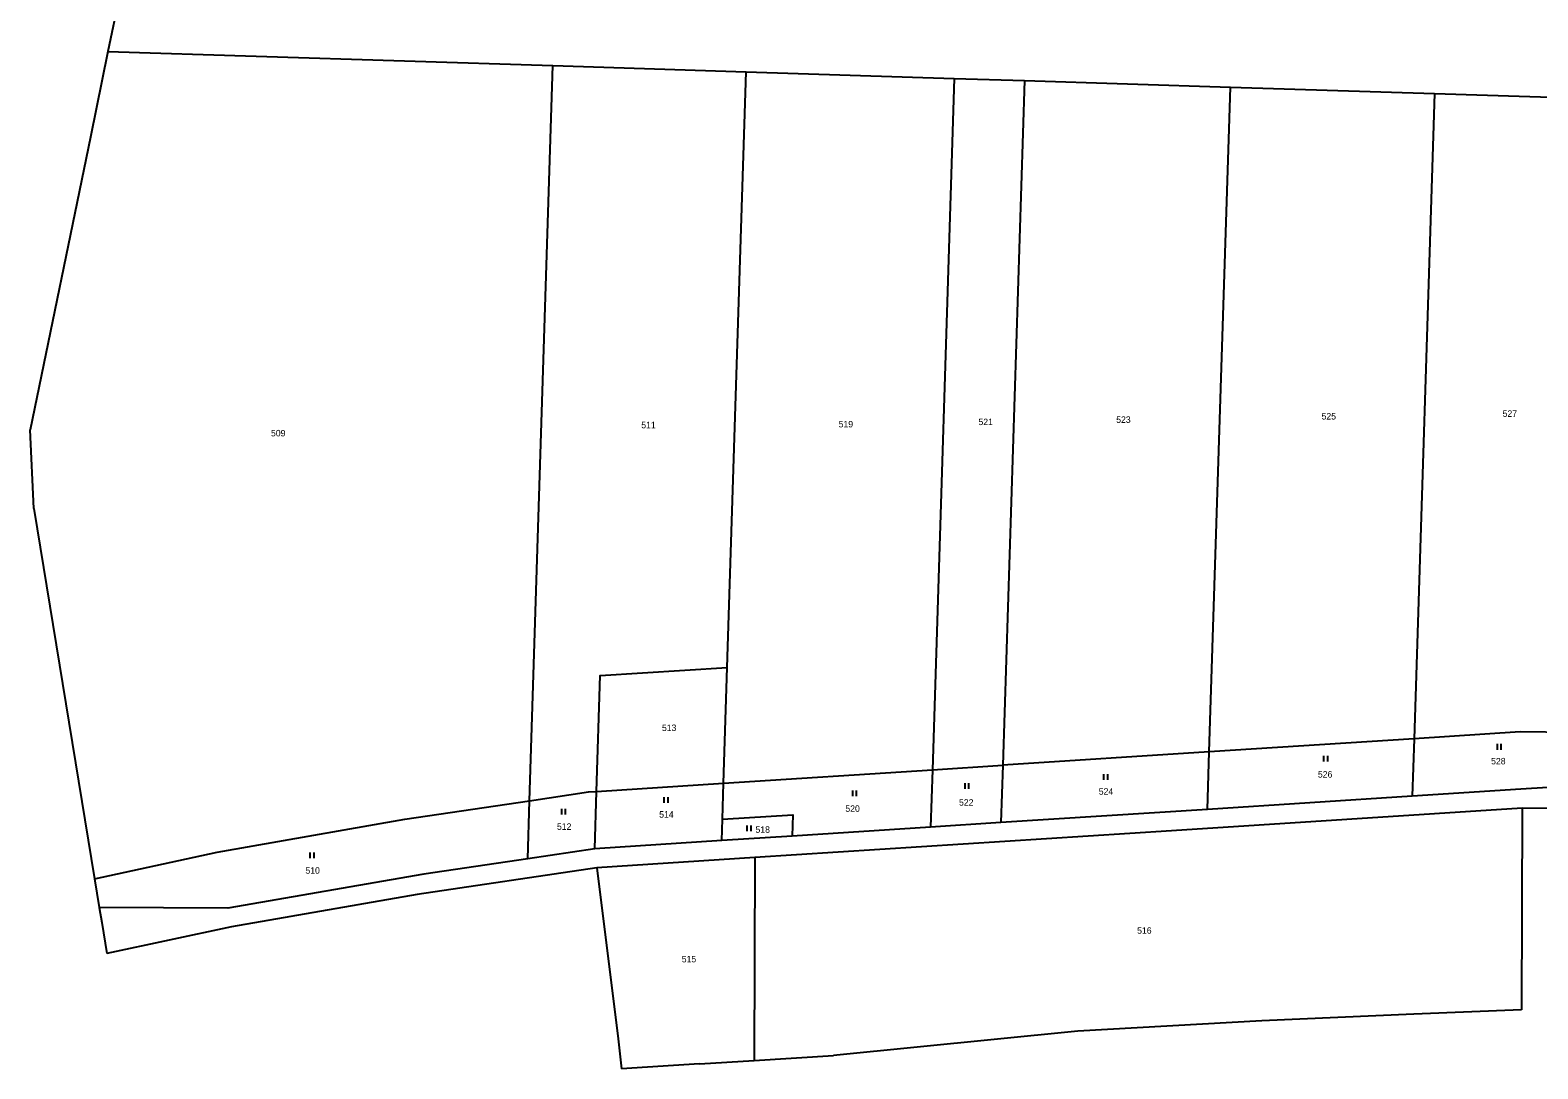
# Model space of a CAD drawing. Extents: x -769392 to -767038, y -1018329 to -1015269.
# Drawn here: x -769392 to -768996.5, y -1017972.4 to -1017699.9 of the extents above; entities that cross this region are included whole.
import ezdxf

# ---------------------------------------------------------------- set-up
doc = ezdxf.new("R2010")
doc.units = 0
doc.header["$LTSCALE"] = 0.68
doc.layers.add('1', color=7, linetype='Continuous', lineweight=25)
doc.layers.add('3', color=7, linetype='Continuous', lineweight=25)
doc.layers.add('2', color=7, linetype='Continuous')

msp = doc.modelspace()

# ---------------------------------------------------------------- linework, layer by layer
at = {"layer": '1'}
for p, q in [((-769362.91, -1017663.26), (-769371.61, -1017705.53)), ((-769371.61, -1017705.53), (-769376.23, -1017728.01)), ((-769371.61, -1017705.53), (-769254.89, -1017709.24)), ((-769261.02, -1017902.07), (-769254.89, -1017709.24)), ((-769254.89, -1017709.24), (-769204.18, -1017710.85)), ((-769209.14, -1017867.11), (-769204.18, -1017710.85)), ((-769204.18, -1017710.85), (-769149.58, -1017712.58)), ((-769149.58, -1017712.58), (-769155.35, -1017893.96)), ((-769149.58, -1017712.58), (-769131.16, -1017713.17)), ((-769131.16, -1017713.17), (-769136.87, -1017892.77)), ((-769131.16, -1017713.17), (-769077.17, -1017714.88)), ((-769082.71, -1017889.28), (-769077.17, -1017714.88)), ((-769077.17, -1017714.88), (-769023.57, -1017716.59)), ((-769023.57, -1017716.59), (-769028.95, -1017885.82)), ((-769023.57, -1017716.59), (-768982.47, -1017717.89)), ((-769376.23, -1017728.01), (-769392.03, -1017804.81)), ((-769391.03, -1017825.39), (-769392.03, -1017804.81)), ((-769391.03, -1017825.39), (-769375.12, -1017922.54)), ((-769210.11, -1017897.48), (-769209.14, -1017867.11)), ((-769028.95, -1017885.82), (-769082.71, -1017889.28)), ((-769028.95, -1017885.82), (-769029.43, -1017900.88)), ((-769082.71, -1017889.28), (-769136.87, -1017892.77)), ((-769083.19, -1017904.34), (-769082.71, -1017889.28)), ((-769155.35, -1017893.96), (-769136.87, -1017892.77)), ((-769136.87, -1017892.77), (-769137.35, -1017907.83)), ((-769243.44, -1017899.63), (-769210.11, -1017897.48)), ((-769210.41, -1017906.94), (-769210.11, -1017897.48)), ((-769210.11, -1017897.48), (-769155.35, -1017893.96)), ((-769155.35, -1017893.96), (-769155.83, -1017909.02)), ((-769243.92, -1017914.69), (-769243.44, -1017899.63)), ((-769029.43, -1017900.88), (-769083.19, -1017904.34)), ((-769261.5, -1017917.31), (-769261.02, -1017902.07)), ((-769083.19, -1017904.34), (-769137.35, -1017907.83)), ((-769000.63, -1017904.04), (-769000.79, -1017956.9)), ((-768915.3, -1017904.97), (-769000.63, -1017904.04)), ((-769210.59, -1017912.55), (-769210.41, -1017906.94)), ((-769155.83, -1017909.02), (-769192.11, -1017911.36)), ((-769137.35, -1017907.83), (-769155.83, -1017909.02)), ((-769210.59, -1017912.55), (-769243.92, -1017914.69)), ((-769192.11, -1017911.36), (-769210.59, -1017912.55)), ((-769243.92, -1017914.69), (-769261.5, -1017917.31)), ((-769201.9, -1017917), (-769243.41, -1017919.67)), ((-769201.9, -1017917), (-769202.06, -1017970.24)), ((-769243.41, -1017919.67), (-769290.52, -1017926.69)), ((-769243.41, -1017919.67), (-769237.81, -1017964.54)), ((-769375.12, -1017922.54), (-769373.89, -1017930.06)), ((-769290.52, -1017926.69), (-769339.19, -1017935.17)), ((-769373.89, -1017930.06), (-769373.24, -1017934.01)), ((-769373.24, -1017934.01), (-769371.9, -1017942.19)), ((-769339.19, -1017935.17), (-769371.9, -1017942.19)), ((-769000.79, -1017956.9), (-769029.05, -1017958.03)), ((-769068.94, -1017959.81), (-769117.2, -1017962.52)), ((-769029.05, -1017958.03), (-769068.94, -1017959.81)), ((-769237.81, -1017964.54), (-769236.89, -1017972.41)), ((-769117.2, -1017962.52), (-769181.25, -1017968.94)), ((-769202.06, -1017970.24), (-769181.25, -1017968.94)), ((-769216.4, -1017971.13), (-769236.89, -1017972.41)), ((-769216.4, -1017971.13), (-769202.06, -1017970.24))]:
    msp.add_line(p, q, dxfattribs=at)
for points in [[(-769243.44, -1017899.63), (-769242.47, -1017869.25), (-769209.14, -1017867.11)], [(-768987.76, -1017884.18), (-769001.16, -1017884.03), (-769028.95, -1017885.82)], [(-769261.02, -1017902.07), (-769245.51, -1017899.76), (-769243.44, -1017899.63)], [(-768988.2, -1017898.24), (-769000.95, -1017899.05), (-769029.43, -1017900.88)], [(-769375.12, -1017922.54), (-769343.01, -1017915.53), (-769293.71, -1017906.95), (-769261.02, -1017902.07)], [(-769000.63, -1017904.04), (-769092.58, -1017909.96), (-769201.9, -1017917)], [(-769210.41, -1017906.94), (-769191.94, -1017905.75), (-769192.11, -1017911.36)], [(-769261.5, -1017917.31), (-769288.71, -1017921.36), (-769340.14, -1017930.26), (-769373.89, -1017930.06)]]:
    msp.add_lwpolyline(points, dxfattribs=at)
at = {"layer": '3'}
for p, q in [((-769007.121, -1017888.69), (-769007.121, -1017887.19)), ((-769006.12, -1017888.69), (-769006.12, -1017887.19)), ((-769052.621, -1017891.83), (-769052.621, -1017890.33)), ((-769051.62, -1017891.83), (-769051.62, -1017890.33)), ((-769146.761, -1017899), (-769146.761, -1017897.5)), ((-769145.76, -1017899), (-769145.76, -1017897.5)), ((-769110.341, -1017896.6), (-769110.341, -1017895.1)), ((-769109.34, -1017896.6), (-769109.34, -1017895.1)), ((-769225.661, -1017902.63), (-769225.661, -1017901.13)), ((-769224.66, -1017902.63), (-769224.66, -1017901.13)), ((-769176.211, -1017900.87), (-769176.211, -1017899.37)), ((-769175.21, -1017900.87), (-769175.21, -1017899.37)), ((-769252.571, -1017905.66), (-769252.571, -1017904.16)), ((-769251.57, -1017905.66), (-769251.57, -1017904.16)), ((-769203.911, -1017910.05), (-769203.911, -1017908.55)), ((-769202.91, -1017910.05), (-769202.91, -1017908.55)), ((-769318.561, -1017917.17), (-769318.561, -1017915.67)), ((-769317.56, -1017917.17), (-769317.56, -1017915.67))]:
    msp.add_line(p, q, dxfattribs=at)

# ---------------------------------------------------------------- texts
at = {"layer": '2'}
for s, p in [('511', (-769231.71, -1017804.375)), ('519', (-769179.93, -1017804.145)), ('521', (-769143.25, -1017803.545)), ('523', (-769107.11, -1017802.955)), ('525', (-769053.24, -1017802.075)), ('527', (-769005.75, -1017801.375)), ('509', (-769328.85, -1017806.505)), ('513', (-769226.29, -1017883.795)), ('528', (-769008.76, -1017892.545)), ('526', (-769054.2, -1017896.005)), ('522', (-769148.35, -1017903.375)), ('524', (-769111.69, -1017900.495)), ('514', (-769227.01, -1017906.515)), ('520', (-769178.16, -1017904.985)), ('512', (-769253.83, -1017909.715)), ('518', (-769201.75, -1017910.495)), ('510', (-769319.82, -1017921.225)), ('516', (-769101.62, -1017936.965)), ('515', (-769221.09, -1017944.475))]:
    msp.add_text(s, height=1.7, dxfattribs=at).set_placement(p)

doc.saveas('drawing.dxf')
